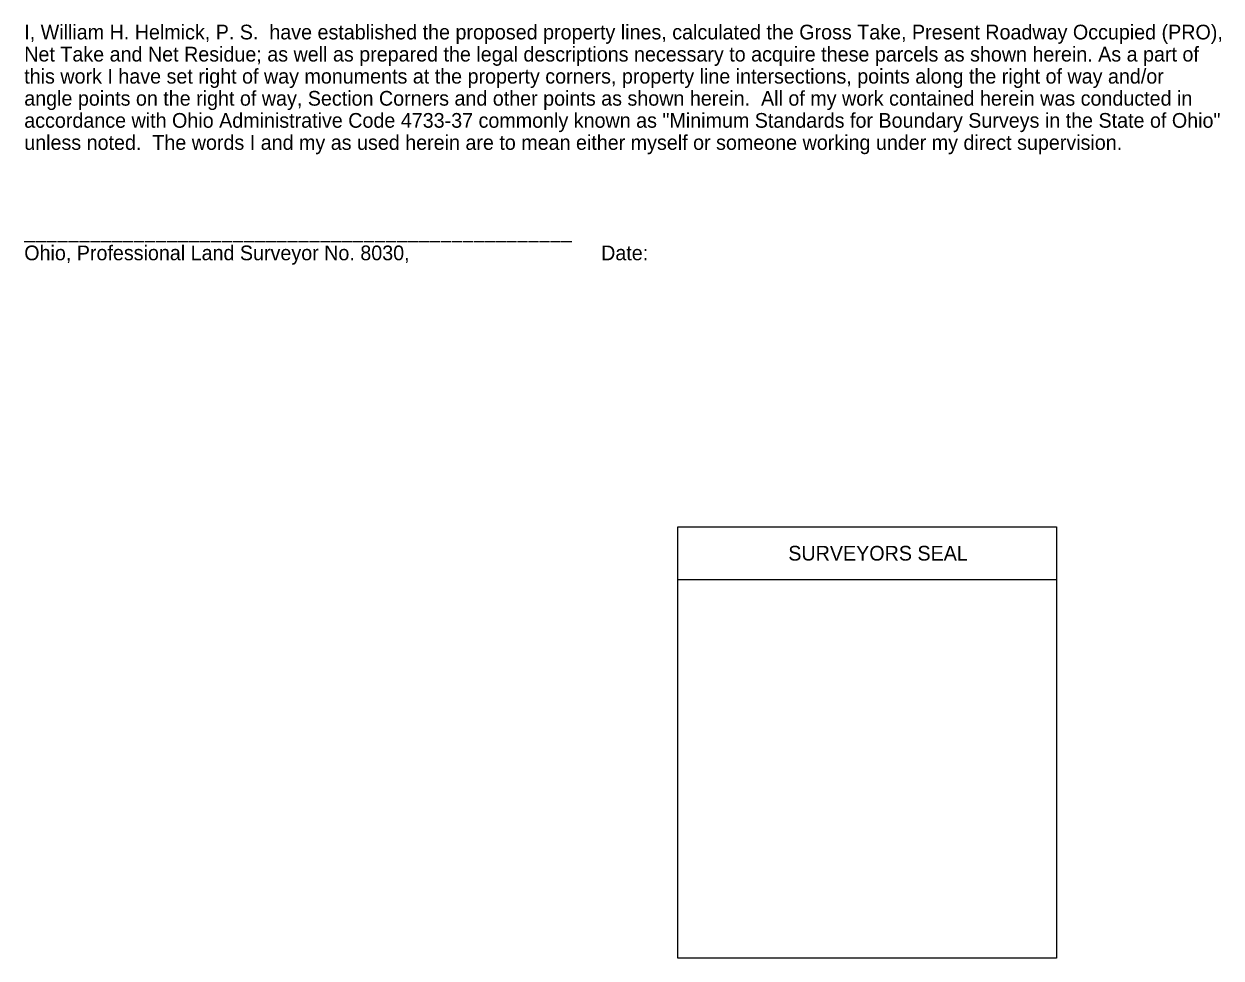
# Model space of a CAD drawing. Extents: x 0 to 1052, y -194 to 246.
# Drawn here: x 45.47 to 56.85, y -1.47 to 7.41 of the extents above; entities that cross this region are included whole.
import ezdxf

# ---------------------------------------------------------------- set-up
doc = ezdxf.new("R2010")
doc.units = 0
doc.layers.add('SH_Data', color=7, linetype='Continuous')
doc.layers.add('SH_Text', color=7, linetype='Continuous')

msp = doc.modelspace()

# ---------------------------------------------------------------- linework, layer by layer
at = {"layer": 'SH_Data'}
msp.add_line((51.689, 2.13), (55.289, 2.13), dxfattribs=at)
msp.add_lwpolyline([(51.689, 2.63), (55.289, 2.63), (55.289, -1.47), (51.689, -1.47)], close=True, dxfattribs=at)

# ---------------------------------------------------------------- texts
msp.add_text('SURVEYORS SEAL', height=0.14, dxfattribs=at).set_placement((52.739, 2.31))
at = {"layer": 'SH_Text'}
for s, p in [('I, William H. Helmick, P. S.  have established the proposed property lines, calculated the Gross Take, Present Roadway Occupied (PRO),', (45.476, 7.266)), ('Net Take and Net Residue; as well as prepared the legal descriptions necessary to acquire these parcels as shown herein. As a part of', (45.476, 7.056)), ('this work I have set right of way monuments at the property corners, property line intersections, points along the right of way and/or', (45.476, 6.846)), ('angle points on the right of way, Section Corners and other points as shown herein.  All of my work contained herein was conducted in', (45.476, 6.636)), ('accordance with Ohio Administrative Code 4733-37 commonly known as "Minimum Standards for Boundary Surveys in the State of Ohio"', (45.476, 6.426)), ('unless noted.  The words I and my as used herein are to mean either myself or someone working under my direct supervision.', (45.476, 6.216)), ('__________________________________________________', (45.476, 5.376)), ('Ohio, Professional Land Surveyor No. 8030,                                   Date:                                     ', (45.476, 5.166))]:
    msp.add_text(s, height=0.14, dxfattribs=at).set_placement(p)

doc.saveas('drawing.dxf')
